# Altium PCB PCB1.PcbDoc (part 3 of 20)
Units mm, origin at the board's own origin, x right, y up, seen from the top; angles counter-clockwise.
Board outline 294.51 x 138.18 mm, 12 copper layers (Top Layer 1 _Signal, L2_GND, L3_Signals, L4_GND, L5_POWER, L6_Signals, L7_GND, L8_Signals, L9_GND, L10_POWER, L11_GND, Bottom Layer_Signals), stack 1.788 mm thick; 1254 components, 836 nets, 5699 pads, 2073 vias.
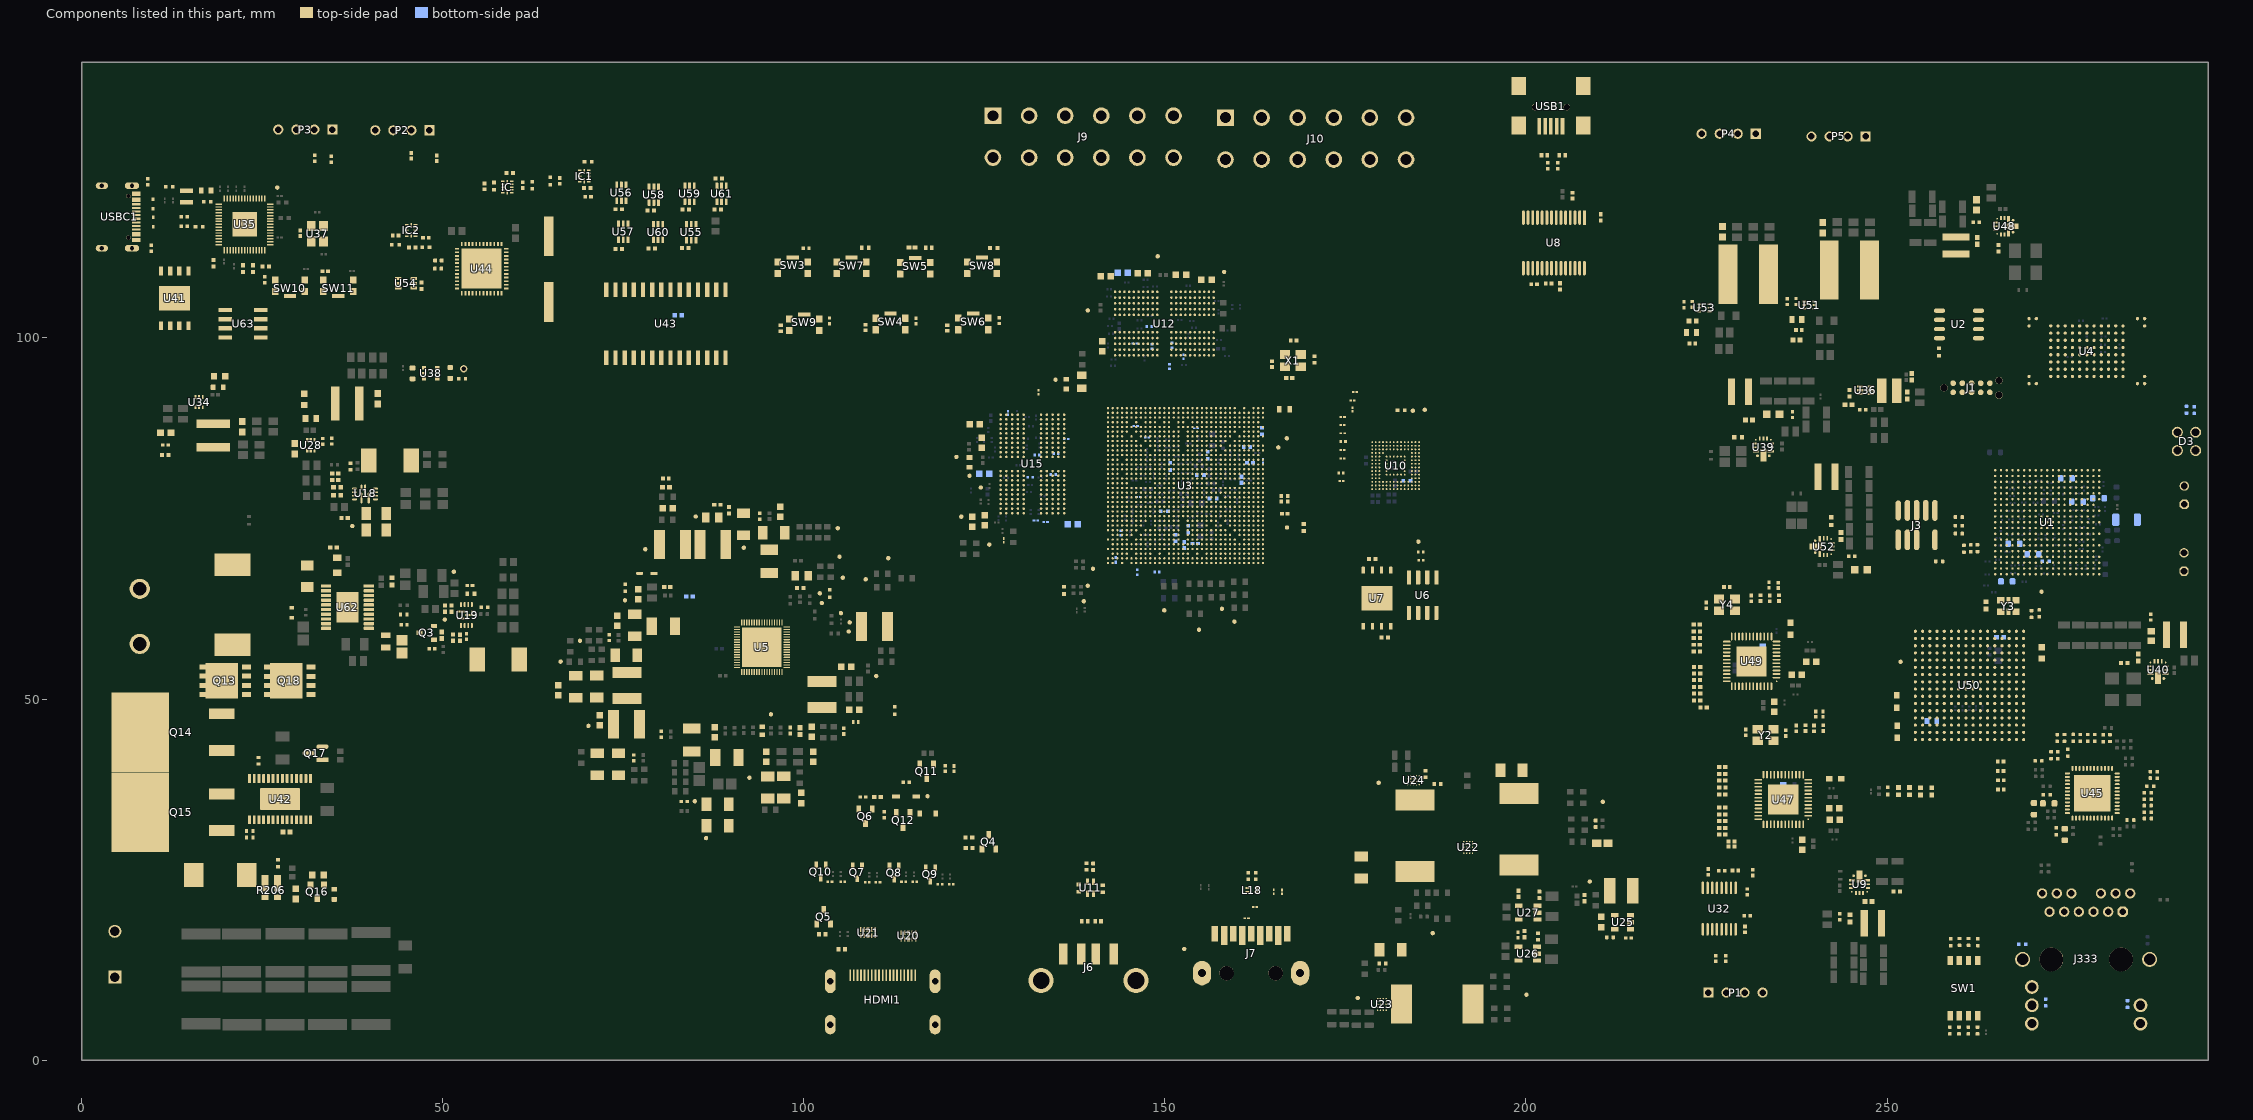
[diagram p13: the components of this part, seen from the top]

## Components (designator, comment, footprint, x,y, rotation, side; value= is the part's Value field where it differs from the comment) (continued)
C682 "GRM188R72A104KA35D" FP-GRM188-0_1-e0_2_0_5-IPC_B 227.217,114.688 r90 top
C683 "C0402C104M3PAC7867" FP-C0402-BB-MFG 47.673,113.869 r0 top value="0.10 μF"
C684 "C0402C104M3PAC7867" FP-C0402-BB-MFG 43.469,114.181 r180 top value="0.10 μF"
C685 "1uf 16V 0402" FP-CC0402-MFG 47.68,112.544 r0 top value="1 uF"
C686 "1uf 16V 0402" FP-CC0402-MFG 43.466,112.879 r180 top value="1 uF"
CN1 "DB910-7.62-2P-GN-S" CONN-TH_2P-P7.62_DB910-7.62-2P 7.239,61.742 r270 top value=30A
D1 "RF2945-000" FP-SESD0402-MFG 107.194,46.827 r0 top value=0.1pF
D2 "1N4148WS" FP-477AB-IPC_C 78.266,67.392 r180 top
D3 "LED_Dual_553-0123" DIO_LED_DUAL_553-0123 291.469,85.671 r270 top value="GREEN, YELLOW"
D4 "NSVR0320MW2T1G" ONSC-SOD-323-2-477-02_V 117.174,34.13 r180 top
D5 "LESD5D5.0CT1G" TVS_LESD5D5.0CT1G 9.875,118.545 r270 top
D6 "LESD5D5.0CT1G" TVS_LESD5D5.0CT1G 9.918,116.055 r270 top
D7 "B5819WS" FAIR-SOD-323_V 114.174,36.514 r180 top
D9 "BAS516,315" FP-SOD523-MFG 29.084,61.937 r90 top
D13 "5.0SMDJ60A" SMC_L6.9-W5.9-LS7.9-RD 19.187,25.64 r180 top
FB1 "Ferrite Bead" IND_C_0603 274.839,80.537 r0 bottom value=120R
FB2 "Ferrite Bead" IND_C_0603 279.288,77.807 r0 bottom value=33R
FB3 "Ferrite Bead" IND_C_0603 270.207,70.029 r180 bottom value=120R
FB4 "Ferrite Bead" IND_C_0603 276.364,77.334 r0 bottom value=120R
FB5 "Ferrite Bead" IND_C_0603 267.571,71.513 r180 bottom value=120R
FB6 "Ferrite Bead" IND_C_0603 266.581,66.293 r180 bottom value=120R
FB7 "Ferrite Bead" IND_C_1206 283.173,74.822 r180 bottom value=120R
FB9 "BLM18KG121TN1D" FP-BLM18-0_15-t0_6-d1_2-IPC_A 210.587,30.046 r180 top
FB24 "Ferrite Bead" IND_C_0603 272.379,35.539 r180 top value=120R
FB25 "Ferrite Bead" IND_C_0603 274.616,31.242 r90 top value=120R
FB26 "Ferrite Bead" IND_C_0603 270.349,34.789 r90 top value=120R
HDMI1 "" HDMI-SMD_HDMI-019S 110.926,6.417 r0 top
IC "NTS0104GU12,115" QFN40P170X200X50-12N 58.94,120.892 r0 top
IC1 "NTS0104GU12,115" QFN40P170X200X50-12N 69.602,122.418 r180 top
IC2 "NTS0104GU12,115" QFN40P170X200X50-12N 45.642,114.893 r180 top
J1 "CON-10P-TC2050-SMT-NO-LEGS" "CON_TAG TC2050 10P NO LEGS" 261.696,93.097 r0 top
J2 "Header 1x2" HDR_M_2.54_1x2 291.128,67.7 r90 top value="HDR-2.54 Male 1x2"
J3 "Header 2x5 POS 7 POLARIZED" HDR_M_1.27_2x5_SMD_V_SAM_FTSH-105-01-F-DV-007-K 254.091,74.08 r0 top value=FTSH-105-01-F-DV-007-K-P-TR
J5 "JUMPER" JUMPER 169.237,73.805 r180 top
J6 "62900416021" 62900416021 139.427,7.747 r0 top
J7 "692122030100" 692122030100 161.941,8.592 r0 top
J8 "1714955" PHOE-1714955_V 4.603,14.663 r90 top
J9 "B12P-XL(LF)(SN)" FP-B12P-XL_LF_SN-MFG 138.7,129.693 r180 top
J10 "B12P-XL(LF)(SN)" FP-B12P-XL_LF_SN-MFG 170.895,129.424 r180 top
J34 "Header 1x2" HDR_M_2.54_1x2 291.166,76.956 r90 top value="HDR-2.54 Male 1x2"
J333 "CON_RJ-45_L829-1J1T-43" CON_JACK_RJ45_L829-1J1T-43 270.056,7.59 r0 top value="MODULAR RJ45"
L1 "0.22uH/12A" FP-FDSD0415-MFG 89.342,41.892 r180 top
L2 "0.47uH/4A" FP-NRS5030-H_3_1-MFG 75.463,46.5 r180 top
L3 "0.47uH/4A" FP-NRS5030-H_3_1-MFG 81.831,71.37 r180 top
L4 "0.47uH/4A" FP-NRS5030-H_3_1-MFG 87.407,71.405 r180 top
L5 "0.22uH/12A" FP-FDSD0415-MFG 80.549,60.065 r180 top
L6 "XAL5030-222MEB" FP-XAL5030-222MEB-MFG 36.798,90.902 r0 top
L7 "0.47uH/4A" FP-NRS5030-H_3_1-MFG 102.538,50.641 r270 top
L8 "1uH 10A" WE-MAPI_4020 229.637,92.543 r0 top
L9 "1.5uH" WE-MAPI_3020 250.312,92.705 r0 top
L10 "0.47uH/4A" FP-NRS5030-H_3_1-MFG 109.772,60.058 r180 top
L11 "0.22uH/12A" FP-FDSD0415-MFG 84.503,44.343 r270 top
L12 "0.22uH/12A" FP-FDSD0415-MFG 95.231,69.067 r90 top
L13 "0.47uH/4A" FP-NRS5030-H_3_1-MFG 75.506,51.85 r90 top
L14 "2.2uH" FP-XAL5030-222MEB-MFG 18.227,86.488 r270 top
L15 "1uH 10A" WE-MAPI_4020 248.03,18.943 r180 top
L16 "1.5uH" IND-SMD_L7.1-W6.6 42.702,83.053 r0 top
L17 "1.5uH" IND-SMD_L7.1-W6.6 57.676,55.493 r0 top
L18 "MCZ1210AH900L2TA0G" FP-MCZ1210AH-MFG 162.054,23.542 r270 top
L19 "220nH" WE-HCC_1210 199.038,31.976 r90 top
L20 "220nH" WE-HCC_1210 187.688,7.77 r0 top
L21 "220nH" WE-HCC_1210 184.635,31.065 r270 top
L22 "2.2uH" IND-SMD_L4.0-W4.0 213.209,23.452 r180 top
L23 "1uH 10A" WE-MAPI_4020 289.859,58.913 r180 top
L24 "1uH 10A" WE-MAPI_4020 259.539,112.779 r90 top
L25 "3.3uH 800mA" FP-CB2016-MFG 14.491,119.587 r90 top
L26 "1uH 10A" WE-MAPI_4020 241.62,80.769 r0 top
L27 "SRN8040-2R2Y" BOUR-SRN8040_V 244.786,109.393 r0 top
L28 "SRN8040-2R2Y" BOUR-SRN8040_V 230.77,108.823 r0 top
L29 "SRP1265A-1R8M" FP-SRP1265A-MFG 20.896,63.05 r90 top value=1.8uH
P1 "S4B-XH-A(LF)(SN)" JST-S4B-XH-A(LF)(SN)_V 229.02,9.345 r0 top
P2 "S4B-XH-A(LF)(SN)" JST-S4B-XH-A(LF)(SN)_V 44.42,128.751 r180 top
P3 "S4B-XH-A(LF)(SN)" JST-S4B-XH-A(LF)(SN)_V 30.982,128.853 r180 top
P4 "S4B-XH-A(LF)(SN)" JST-S4B-XH-A(LF)(SN)_V 228.072,128.272 r180 top
P5 "S4B-XH-A(LF)(SN)" JST-S4B-XH-A(LF)(SN)_V 243.29,127.892 r180 top
Q3 "SS8050-G" FP-SS8050-G-MFG 47.782,59.157 r180 top
Q4 "2SK3018" SOT-23-3_L2.9-W1.3-P1.90-LS2.4-BR 547.187,460.843 r270 top
Q5 "2SK3018" SOT-23-3_L2.9-W1.3-P1.90-LS2.4-BR 524.315,450.472 r270 top
Q6 "2SK3018" SOT-23-3_L2.9-W1.3-P1.90-LS2.4-BR -313.018,-396.862 r90 top
Q7 "WNM6002-3/TR" SOT-323-3_L2.0-W1.3-P1.30-LS2.1-BR -235.455,-430.948 r90 top
Q8 "WNM6002-3/TR" SOT-323-3_L2.0-W1.3-P1.30-LS2.1-BR -230.348,-430.985 r90 top
Q9 "WNM6002-3/TR" SOT-323-3_L2.0-W1.3-P1.30-LS2.1-BR -225.329,-431.241 r90 top
Q10 "WNM6002-3/TR" SOT-323-3_L2.0-W1.3-P1.30-LS2.1-BR -240.485,-430.836 r90 top
Q11 "2SK3018" SOT-23-3_L2.9-W1.3-P1.90-LS2.4-BR -304.538,-390.614 r90 top
Q12 "2SK3018" SOT-23-3_L2.9-W1.3-P1.90-LS2.4-BR -307.813,-397.382 r90 top
Q13 "CSD18540Q5B" VSON-CLIP-8_L5.0-W6.0-P1.27-BL 19.88,52.514 r90 top
Q14 "PSMN4R8" TO-263-2_L10.2-W8.5-P2.54-LS15.2-TL 12.748,45.416 r180 top
Q15 "PSMN4R8" TO-263-2_L10.2-W8.5-P2.54-LS15.2-TL 12.748,34.317 r180 top
Q16 "2N7002-7-F" FP-SOT23-MFG 32.632,23.314 r270 top
Q17 "MMBT3904-7-F" FP-SOT23-IPC_A 32.377,42.495 r180 top
Q18 "CSD18540Q5B" VSON-CLIP-8_L5.0-W6.0-P1.27-BL 28.828,52.492 r90 top
R1 "Resistor" RES_C_0402 262.522,70.885 r90 top value=10k
R2 "10R 0402" FP-RT0402-MFG 257.201,98.051 r90 top value=10Ω
R3 "100K / 0402" FP-CRGP0402-IPC_C 161.806,82.693 r0 bottom value=100KΩ
R4 "Resistor" RES_C_0402 271.077,61.858 r90 top value=10k
R5 "Resistor" RES_C_0402 259.945,75.196 r180 top value=10k
R6 "Resistor" RES_C_0402 270.003,61.769 r90 top value=10k
R7 "Resistor" RES_C_0402 260.648,70.814 r90 top value=10k
R8 "Resistor" RES_C_0402 257.223,69.053 r0 top value=10k
R9 "0R/0201" FP-RMCF0201-IPC_C 163.589,82.97 r90 bottom
R10 "Resistor" RES_C_0402 262.524,4.097 r90 top value=1k
R11 "Resistor" RES_C_0402 259.945,74.011 r0 top value=0R
R12 "Resistor" RES_C_0402 261.254,4.097 r90 top value=1k
R13 "Resistor" RES_C_0402 259.971,4.097 r90 top value=1k
R14 "Resistor" RES_C_0402 259.945,72.911 r0 top value=0R
R15 "Resistor" RES_C_0402 258.701,4.097 r90 top value=1k
R16 "Resistor" RES_C_0402 262.573,16.336 r270 top value=10k
R17 "Resistor" RES_C_0402 261.29,16.359 r270 top value=10k
R18 "Resistor" RES_C_0402 260.043,16.359 r270 top value=10k
R19 "Resistor" RES_C_0402 258.82,16.324 r270 top value=10k
R20 "120K 5% 0402(1005)" RESC0402(1005)_M 94.228,45.592 r90 top value="120000.00 Ohm"
R21 "Resistor" RES_C_0402 292.547,90.016 r270 bottom value=1k
R22 "Resistor" RES_C_0402 291.467,90.063 r270 bottom value=1k
R23 "510k/0402" RESC1005X40X25NL05T10 167.219,94.436 r0 top
R24 "22R2J" RESC0402(1005)_L#1 163.437,87.128 r90 bottom value=22
R25 "22R2J" RESC0402(1005)_L#1 161.349,84.868 r180 bottom value=22
R26 "22R2J" RESC0402(1005)_L#1 170.71,97.029 r270 top value=22
R27 "49.9R 0201" FP-AF0201-MFG 134.547,81.112 r180 bottom
R28 "100R / 0402" FP-MCS0402-IPC_C 80.239,45.119 r270 top
R29 "100R / 0402" FP-MCS0402-IPC_C 76.471,41.854 r90 top
R30 "0R 0805" FP-AF0805-IPC_B 99.72,67.063 r180 top
R31 "0R 0805" FP-AF0805-IPC_B 87.311,75.116 r0 top
R32 "120k/0402/1%" RESC1005X40X25ML05T10 80.902,79.316 r180 top
R33 "100k / 0402" FP-CRGP0402-IPC_C 88.031,76.916 r0 top value=100KΩ
R34 "100R / 0402" FP-MCS0402-IPC_C 73.057,58.506 r270 top
R35 "20k/0402" RESC1005X40X25ML10T10 99.502,45.562 r270 top
R36 "100R / 0402" FP-MCS0402-IPC_C 83.446,35.814 r0 top
R37 "100k / 0402" FP-CRGP0402-IPC_C 98.108,45.637 r90 top value=100KΩ
R38 "100R / 0402" FP-MCS0402-IPC_C 93.921,75.299 r90 top
R39 "200K/0402" FP-AC0402-IPC_B 81.109,65.534 r180 top
R40 "200K/0402" FP-AC0402-IPC_B 84.184,64.197 r0 bottom
R41 "10K/0402" RESC1005X40X20NL05T10 99.507,65.402 r0 top
R42 "DNP" RES_C_0402 261.611,70.865 r270 top value=10k
R43 "1.82K" FP-CRCW0402-e3-IPC_A 244.856,19.632 r90 top
R44 "10K/0201" RESC0603X28X15LL05T05 145.858,99.212 r0 bottom
R45 "10K/0201" RESC0603X28X15LL05T05 152.588,97.414 r90 bottom
R46 "240R/0201" FP-RMCF0201-IPC_C 128.259,89.591 r90 bottom
R47 "240R/0201" FP-RMCF0201-IPC_C 132.509,92.481 r90 top
R48 "10K/0201" RESC0603X28X15LL05T05 127.687,71.951 r270 top
R49 "10K/0201" RESC0603X28X15LL05T05 136.359,85.993 r180 bottom
R50 "10KR 0402" RESC1005X40X25ML05T10 247.442,21.954 r0 top
R51 "240R/0201" FP-RMCF0201-IPC_C 133.497,74.534 r0 bottom
R52 "4.87K 0402" FP-CRCW0402-e3-IPC_C 243.456,19.856 r90 top
R53 "11.5K 0402" RESC1005X40X25NL05T05 251.33,23.356 r180 top
R54 "1.21K 0603" FP-RMCF0603-IPC_B 262.362,118.421 r270 top
R55 "100KR 0402" FP-CRCW0402-e3-IPC_C 34.635,85.707 r270 top
R56 "0R/0201" FP-RMCF0201-IPC_C 174.628,86.796 r180 top
R57 "0R/0201" FP-RMCF0201-IPC_C 174.622,89.049 r180 top
R58 "0R/0201" FP-RMCF0201-IPC_C 175.975,91.348 r180 top
R59 "0R/0201" FP-RMCF0201-IPC_C 174.597,83.315 r180 top
R60 "0R/0201" FP-RMCF0201-IPC_C 174.477,80.176 r180 top
R61 "0R/0201" FP-RMCF0201-IPC_C 175.985,90.087 r90 top
R62 "0R/0201" FP-RMCF0201-IPC_C 174.594,84.489 r180 top
R63 "0R/0201" FP-RMCF0201-IPC_C 174.616,87.923 r180 top
R64 "0R/0201" FP-RMCF0201-IPC_C 176.324,92.5 r180 top
R65 "RT0201BRE0710KL" FP-RT0201-MFG 174.689,85.639 r0 top value=10KΩ
R66 "10k 0402" FP-CRGCQ0402-IPC_C 166.599,75.652 r0 top value=10KΩ
R67 "RT0201BRE0710KL" FP-RT0201-MFG 174.389,81.322 r0 top value=10KΩ
R68 "22R2J" RESC0402(1005)_L#1 166.58,78.119 r180 top value=22
R69 "47D5KR2F" RESC0402(1005)_L#1 166.571,77.341 r0 top value=47.5k
R70 "0R/0201" FP-RMCF0201-IPC_C 146.329,77.949 r0 bottom
R71 "240R/0201" FP-RMCF0201-IPC_C 132.135,74.734 r0 bottom
R72 "10K/0402" RESC1005X40X20NL05T10 180.434,58.519 r0 top
R73 "10K/0402" RESC1005X40X20NL05T10 178.719,69.357 r180 top
R74 "0R 0402" FP-AF0402-MFG 138.098,23.812 r270 top
R75 "100k/0402" RESC1005X40X25NL05T10 36.413,75.068 r0 top
R76 "30k/0402/0.1%" RESC1005X35X20ML05T10 35.371,79.314 r180 top
R77 "232k 0402" RESC1005X40X25ML05T05 35.377,78.226 r0 top
R78 "3D3R2J" RESC0402(1005)_L#1 37.244,82.217 r90 top value=3.3
R79 "100k/0402" RESC1005X40X25NL05T10 35.13,80.322 r180 top
R80 "100k/0402" RESC1005X40X25NL05T10 35.125,81.242 r180 top
R81 "510k/0402" RESC1005X40X25NL05T10 51.208,62.519 r270 top
R82 "3D3R2J" RESC0402(1005)_L#1 55.787,62.708 r0 top value=3.3R
R83 "100k/0402" RESC1005X40X25NL05T10 51.435,58.501 r90 top
R84 "43k/0402" FP-AC0402-MFG 53.898,64.597 r0 top
R85 "100k/0402" RESC1005X40X25NL05T10 52.39,58.492 r90 top
R86 "100k/0402" RESC1005X40X25NL05T10 50.29,62.528 r90 top
R87 "10K/0402" RESC1005X40X25LL05T10 53.314,58.636 r90 top
R88 "7.5k/0402" RESC1005X40X25LL05T10 53.758,65.728 r180 top
R89 "10K/0402" RESC1005X40X25LL05T10 48.525,56.972 r180 top
R90 "Resistor 51k +/-5% 0402 63 mW" RESC1005X40X25ML05T10 49.887,58.829 r270 top value=51k
R91 "200R/0201" FP-RT0201-MFG 148.92,67.58 r0 bottom value=200Ω
R92 "0R/0201" FP-RMCF0201-IPC_C 161.325,19.636 r0 top
R93 "2R2/0402" RESC0402(1005)_L#1 161.547,25.516 r270 top
R94 "2R2/0402" RESC0402(1005)_L#1 162.586,25.511 r270 top
R95 "0R/0201" FP-RMCF0201-IPC_C 162.483,21.225 r180 top
R96 "0R/0201" FP-RMCF0201-IPC_C 166.233,23.302 r270 top
R97 "0R/0201" FP-RMCF0201-IPC_C 165.076,23.31 r270 top
R98 "8.2K/0201" RESC0603X26X15ML03T05 154.22,71.545 r180 bottom
R99 "8.2K/0201" RESC0603X28X15NL05T05 143.229,69.273 r90 bottom
R100 "47K/0402" FP-CRCW0402-e3-IPC_B 122.871,30.84 r180 top
R101 "Resistor" RES_C_0402 271.996,69.096 r0 bottom value=10R
R102 "47K/0402" FP-CRCW0402-e3-IPC_B 122.887,29.383 r180 top
R103 "1.2k/0402" FP-RN73R1E-IPC_B 105.258,15.343 r0 top
R104 "200R/0201" FP-RT0201-MFG 143.951,72.998 r270 bottom value=200Ω
R105 "47K/0402" FP-CRCW0402-e3-IPC_B 102.547,17.418 r180 top
R106 "1.8k 0402" FP-RN73R1E-IPC_C 111.121,33.965 r90 top
R107 "10K/0402" RESC1005X40X25LL05T10 108.189,36.447 r180 top
R108 "1.8k 0402" FP-RN73R1E-IPC_C 114.193,38.486 r180 top
R109 "590R 1% 0201(0603)" RESC0201(0603)_L 108.792,24.641 r0 top value="590.00 Ohm"
R110 "590R 1% 0201(0603)" RESC0201(0603)_L 110.254,24.655 r180 top value="590.00 Ohm"
R111 "590R 1% 0201(0603)" RESC0201(0603)_L 113.832,24.72 r0 top value="590.00 Ohm"
R112 "590R 1% 0201(0603)" RESC0201(0603)_L 115.363,24.689 r180 top value="590.00 Ohm"
R113 "1K/0402" FP-AC0402-IPC_C 119.593,40.374 r90 top
R114 "10K/0402" RESC1005X40X25LL05T10 120.813,40.356 r90 top
R115 "590R 1% 0201(0603)" RESC0201(0603)_L 118.863,24.38 r0 top value="590.00 Ohm"
R116 "590R 1% 0201(0603)" RESC0201(0603)_L 120.413,24.354 r180 top value="590.00 Ohm"
R117 "590R 1% 0201(0603)" RESC0201(0603)_L 103.608,24.692 r0 top value="590.00 Ohm"
R118 "590R 1% 0201(0603)" RESC0201(0603)_L 105.394,24.708 r180 top value="590.00 Ohm"
R119 "AC0402FR-7W27KL" FP-AC0402-IPC_B 110.213,36.42 r180 top
R120 "100R / 0402" RESC0402(1005)_L#1 209.651,32.724 r90 top value=100
R121 "100R / 0402" RESC0402(1005)_L#1 180.156,13.384 r0 top value=100
R122 "100k/0402" RESC1005X40X25NL05T10 160.596,80.363 r90 bottom
R123 "120k/0402" RESC0402(1005)_L#1 186.081,39.63 r270 top value=120k
R124 "100R / 0402" RESC0402(1005)_L#1 187.747,38.229 r0 top value=100
R125 "100k/0402" RESC1005X40X25NL05T10 208.107,22.427 r270 top
R126 "10uf/0603" FP-CC0603-DC-MFG 210.42,19.126 r270 top
R127 "10K/0402" RESC1005X40X25LL05T10 214.194,16.917 r180 top
R128 "10K/0402" RESC1005X40X20NL05T10 151.489,72.297 r90 bottom
R129 "120k/0402" RESC0402(1005)_L#1 211.64,17.009 r0 top value=120k
R130 "100K / 0402" FP-CRGP0402-IPC_C 152.673,71.321 r270 bottom value=100KΩ
R131 "4.7k 0402" RESC0402(1005)_L#1 201.671,17.124 r270 top value=4.7k
R132 "4.7k 0402" RESC0402(1005)_L#1 201.875,22.893 r270 top value=4.7k
R133 "10K/0402" RESC1005X40X25LL05T10 198.883,17.318 r90 top
R134 "100k/0402" RESC1005X40X25NL05T10 199.794,17.451 r90 top
R135 "100k/0402" RESC1005X40X25NL05T10 198.999,23.04 r90 top
R136 "220K 0603" RESC1608X55X25ML10T15 31.738,88.845 r0 top
R137 "17.4K" RESC1005X40X25LL05T05 33.409,85.663 r90 top
R138 "30K" FP-AT0603-IPC_B 30.817,91.496 r270 top
R139 "10KR 0402" RESC1005X40X25ML05T10 253.43,94.621 r90 top
R140 "100KR 0402" FP-CRCW0402-e3-IPC_C 246.632,90.062 r0 top
R141 "10KR 0402" RESC1005X40X25ML05T10 252.788,92.035 r90 top
R142 "68.1K 0402" FP-CRCW0402-e3-IPC_B 244.824,92.354 r90 top
R143 "10KR 0402" RESC1005X40X25ML05T10 244.675,90.739 r0 top
R144 "30K" FP-AT0603-IPC_B 19.103,94.7 r0 top
R145 "RT0603BRD07135KL" RESC0603(1608)_L 18.907,93.161 r0 top value=135kΩ
R146 "100KR 0402" FP-CRCW0402-e3-IPC_C 11.62,85.17 r180 top
R147 "CRCW040220K0FKED" FP-CRCW0402-e3-IPC_B 11.575,83.798 r0 top
R148 "Resistor 0R +/- 5% 1206 250 mW" RESC3216X60X45ML15T20 71.419,40.977 r90 top value=0
R149 "HoYH1206-1W-10mR-1%" RESC3216X60X45ML15T20 74.339,40.977 r90 top value=1W
R150 "49.9R 0201" FP-AF0201-MFG 131.361,80.709 r0 bottom
R151 "49.9R 0201" FP-AF0201-MFG 134.917,83.991 r180 bottom
R152 "49.9R 0201" FP-AF0201-MFG 132.283,83.806 r180 bottom
R153 "49.9R 0201" FP-AF0201-MFG 148.217,98.83 r90 bottom
R154 "49.9R 0201" FP-AF0201-MFG 147.848,101.571 r0 bottom
R155 "49.9R 0201" FP-AF0201-MFG 151.015,98.978 r90 bottom
R156 "49.9R 0201" FP-AF0201-MFG 150.661,96.044 r90 bottom
R157 "4.87K 0402" FP-CRCW0402-e3-IPC_C 286.489,61.348 r270 top
R158 "604R 0603" RESC1609X50X30ML10T20 286.586,58.716 r270 top
R159 "11.5K 0402" RESC1005X40X25NL05T05 282.873,54.955 r0 top
R160 "10KR 0402" RESC1005X40X25ML05T10 284.775,55.732 r270 top
R161 "10KR 0402" RESC1005X40X25ML05T10 262.505,113.451 r270 top
R162 "4.87K 0402" FP-CRCW0402-e3-IPC_C 262.362,116.034 r0 top
R163 "11.5K 0402" RESC1005X40X25NL05T05 265.444,112.418 r90 top
R164 "0R/0402" RESC1005X40X25NL05T10 210.356,116.683 r90 top
R165 "0R/0402" RESC1005X40X25NL05T10 204.745,107.141 r90 top
R166 "22R/0402" FP-CRCW0402-e3-IPC_C 204.376,123.832 r90 top
R167 "22R/0402" FP-CRCW0402-e3-IPC_C 203.02,123.853 r90 top
R168 "22R/0402" FP-CRCW0402-e3-IPC_C 227.666,14.073 r270 top
R169 "22R/0402" FP-CRCW0402-e3-IPC_C 226.302,14.073 r270 top
R170 "22R/0402" FP-CRCW0402-e3-IPC_C 230.641,19.986 r0 top
R171 "22R/0402" FP-CRCW0402-e3-IPC_C 230.65,23.287 r90 top
R172 "10K/0402" RESC1005X40X20NL05T10 89.648,76.152 r270 top
R173 "2R2/0402" RESC0402(1005)_L#1 139.133,26.792 r270 top
R174 "2R2/0402" RESC0402(1005)_L#1 140.079,26.775 r270 top
R175 "0R 0402" FP-AF0402-MFG 141.418,23.721 r270 top
R176 "200R/0201" FP-RT0201-MFG 146.177,67.561 r270 bottom value=200Ω
R177 "100R / 0402" FP-MCS0402-IPC_C 100.316,112.425 r180 top
R178 "3K 0402" FP-AT0402-IPC_B 114.984,112.503 r0 top
R179 "100R / 0402" FP-MCS0402-IPC_C 115.538,102.346 r90 top
R180 "6.8K 0402" FP-AC0402-MFG 108.517,112.497 r0 top
R181 "100R / 0402" FP-MCS0402-IPC_C 127.043,102.392 r90 top
R182 "12k 0402" FP-CRCW0402-e3-MFG 126.31,112.457 r180 top
R183 "100R / 0402" FP-MCS0402-IPC_C 103.568,102.363 r90 top
R184 "6.04K  0603" FP-RC0603-0_55-IPC_A 234.229,89.423 r0 top
R185 "10KR 0402" RESC1005X40X25ML05T10 230.889,88.643 r180 top
R186 "4.87K 0402" FP-CRCW0402-e3-IPC_C 236.914,89.383 r270 top
R187 "R220" RESC1005X40X25NL05T10 227.194,39.622 r0 top
R188 "33R 0603" FP-AF0603-IPC_C 17.241,120.431 r180 top
R189 "RC0402JR-100RL" RESC1005X40X25NL05T10 223.671,56.596 r0 top
R190 "5.1K 0402" FP-RN73R1E-IPC_C 9.65,112.393 r270 top value=5.1K
R191 "51R 0402" FP-AF0402-IPC_C 49.205,124.883 r90 top
R192 "5.1K 0402" FP-RN73R1E-IPC_C 9.14,121.649 r270 top value=5.1K
R193 "51R 0402" FP-AF0402-IPC_C 45.634,125.229 r90 top
R194 "3.3K 0402" FP-RN73R1E-IPC_B 23.745,109.611 r270 top
R195 "3.3K 0402" FP-RN73R1E-IPC_B 22.373,109.609 r270 top
R196 "10K/0402" RESC1005X40X20NL05T10 25.509,109.873 r180 top
R197 "1k 0402" FP-MCS0402-IPC_C 25.356,108.062 r90 top
R198 "22R/0402" FP-CRCW0402-e3-IPC_C 14.209,116.782 r0 top
R199 "22R/0402" FP-CRCW0402-e3-IPC_C 14.219,115.455 r0 top
R200 "1k" FP-CRGCQ0402-IPC_C 30.27,114.498 r270 top value=1KΩ
R201 "22R/0402" FP-CRCW0402-e3-IPC_C 34.543,124.751 r90 top
R202 "22R/0402" FP-CRCW0402-e3-IPC_C 32.282,124.881 r90 top
R203 "10K/0402" RESC1005X40X20NL05T10 18.257,110.368 r270 top
R204 "1k" FP-CRGCQ0402-IPC_C 33.765,109.251 r0 top value=1KΩ
R205 "4R99 1% 0402(1005)" RESC0402(1005)_L#2 23.276,30.805 r0 top value="4.99 Ohm"
R206 "0.001R 1206" FP-PS0612-MFG 26.259,23.907 r180 top value=1mΩ
R207 "4R99 1% 0402(1005)" RESC0402(1005)_L#2 23.293,31.72 r0 top value="4.99 Ohm"
R208 "100K 0603" FP-TFCR0603-IPC_B 29.659,23.031 r90 top
R209 "95.3K 0402" FP-RP73P-1E-MFG 27.192,27.268 r270 top value=95.3KΩ
R210 "14.3K 0603" RESC0603(1608)_L 34.974,22.95 r270 top value=14.3K
R211 "8.87K 0402" FP-RC1005-IPC_A 28.382,31.601 r180 top
R212 "28K 1% 0402(1005)" RESC0402(1005)_L#2 24.499,41.437 r90 top value="28000.00 Ohm"
R213 "100K 1% 0603(1608)" RESC0603(1608)_N 32.745,25.635 r0 top value="100000.00 Ohm"
R214 "20K 0402" RESC1005X35X20ML05T10 82.617,103.123 r180 bottom
R215 "11K 0603" FP-RT0603-MFG 242.822,38.969 r0 top value=11KΩ
R216 "RC0402JR-100RL" RESC1005X40X25NL05T10 227.191,36.767 r0 top
R217 "RC0402JR-100RL" RESC1005X40X25NL05T10 228.464,30.245 r0 top
R218 "RC0402JR-100RL" RESC1005X40X25NL05T10 227.198,37.732 r0 top
R219 "RC0402JR-100RL" RESC1005X40X25NL05T10 227.195,38.692 r0 top
R220 "RC0402JR-100RL" RESC1005X40X25NL05T10 223.699,49.789 r0 top
R221 "RC0402JR-100RL" RESC1005X40X25NL05T10 227.193,40.57 r0 top
R222 "RC0402JR-100RL" RESC1005X40X25NL05T10 227.181,34.985 r0 top
R223 "RC0402JR-100RL" RESC1005X40X25NL05T10 228.463,29.561 r0 top
R224 "RC0402JR-100RL" RESC1005X40X25NL05T10 227.177,34.035 r0 top
R225 "RC0402JR-100RL" RESC1005X40X25NL05T10 227.18,33.097 r0 top
R226 "RC0402JR-100RL" RESC1005X40X25NL05T10 227.176,32.157 r0 top
R227 "RC0402JR-100RL" RESC1005X40X25NL05T10 227.176,31.238 r0 top
R228 "12.1R 0402" RESC1005X40X25LL05T10 241.136,47.9 r270 top
R229 "12.1R 0402" RESC1005X40X25LL05T10 240.138,47.9 r270 top
R230 "14.3K 0402" FP-CRCW0402-e3-MFG 229.381,86.236 r0 top
R231 "6.04K  0603" FP-RC0603-0_55-IPC_A 246.4,67.921 r180 top
R232 "10KR 0402" RESC1005X40X25ML05T10 243.626,72.562 r90 top
R233 "4.87K 0402" FP-CRCW0402-e3-IPC_C 245.107,69.749 r180 top
R234 "14.3K 0402" FP-CRCW0402-e3-MFG 242.273,74.632 r270 top
R235 "11K 0603" FP-RT0603-MFG 236.626,59.717 r90 top value=11KΩ
R236 "RC0402JR-100RL" RESC1005X40X25NL05T10 223.663,57.514 r0 top
R237 "RC0402JR-100RL" RESC1005X40X25NL05T10 223.667,58.443 r0 top
R238 "RC0402JR-100RL" RESC1005X40X25NL05T10 223.666,59.369 r0 top
R239 "RC0402JR-100RL" RESC1005X40X25NL05T10 223.658,60.307 r0 top
R240 "RC0402JR-100RL" RESC1005X40X25NL05T10 223.696,54.46 r0 top
R241 "RC0402JR-100RL" RESC1005X40X25NL05T10 224.605,48.819 r0 top
R242 "620R 0603" FP-AC0603-IPC_C 256.217,46.943 r180 bottom
R243 "RC0402JR-100RL" RESC1005X40X25NL05T10 223.695,53.558 r0 top
R244 "RC0402JR-100RL" RESC1005X40X25NL05T10 223.686,52.616 r0 top
R245 "RC0402JR-100RL" RESC1005X40X25NL05T10 223.689,51.676 r0 top
R246 "RC0402JR-100RL" RESC1005X40X25NL05T10 223.689,50.737 r0 top
R247 "Resistor 0R +/- 5% 1206 250 mW" RESC3216X60X45ML15T20 95.01,37.744 r270 top value=0
R248 "HoYH1206-1W-10mR-1%" RESC3216X60X45ML15T20 97.246,37.765 r270 top value=1W
R249 "12.1R 0402" RESC1005X40X25LL05T10 234.952,65.748 r270 top
R250 "4.7k/0402" FP-MCS0402-IPC_A 263.715,62.975 r90 top
R251 "12.1R 0402" RESC1005X40X25LL05T10 233.653,65.774 r270 top
R252 "4.7k/0402" FP-MCS0402-IPC_A 265.659,58.554 r0 bottom
R253 "RMCF0603ZT0R00 0R/0603" FP-RMCF0603-MFG 166.56,90.097 r180 top value=0mΩ
R254 "95.3kΩ 0402" FP-CRCW0402-e3-IPC_A 237.46,99.717 r180 top
R255 "100kΩ, 0402" FP-CRCW0402-e3-IPC_C 236.185,105.031 r90 top
R256 "2K 0603" FP-AC0603-IPC_B 271.409,56.394 r90 top
R257 "4.7k/0402" FP-MCS0402-IPC_A 251.603,37.237 r270 top
R258 "332R 0603" FP-RT0603-MFG 251.344,49.64 r90 top value=332Ω
R259 "4.7k/0402" FP-MCS0402-IPC_A 256.19,37.212 r270 top
R260 "332R 0603" FP-RT0603-MFG 251.412,45.463 r90 top value=332Ω
R261 "4.7k/0402" FP-MCS0402-IPC_A 254.632,37.218 r270 top
R262 "4.7k/0402" FP-MCS0402-IPC_A 253.128,37.246 r270 top
R263 "0R 0805" FP-AF0805-IPC_B 138.491,93.918 r270 top
R264 "0R 0603" FP-AC0603-IPC_C 122.927,82.762 r90 top
R265 "0R 0603" FP-AC0603-IPC_C 136.337,93.613 r270 top
R266 "" FP-MCT0603-MFG 237.515,102.566 r0 top value=30K
R267 "59K 0402" RESC1005X40X25LL05T05 237.411,105.046 r270 top
R268 "95.3kΩ 0402" FP-CRCW0402-e3-IPC_A 223.068,102.324 r180 top
R269 "100kΩ, 0402" FP-CRCW0402-e3-IPC_C 221.885,104.601 r90 top
R270 "" FP-MCT0603-MFG 222.919,100.734 r0 top value=30K
R271 "59K 0402" RESC1005X40X25LL05T05 223.035,104.653 r270 top
R272 "10K/0402" RESC1005X40X20NL05T10 47.089,107.218 r270 top
R273 "10k 0402" RESC1005X40X20NL05T10 45.753,112.527 r180 top
R274 "240R/0201" FP-RMCF0201-IPC_C 147.523,86.186 r180 bottom
R275 "240R/0201" FP-RMCF0201-IPC_C 154.294,87.49 r0 bottom
R276 "10K/0402" RESC1005X40X20NL05T10 83.582,112.43 r180 top
R277 "10k 0402" RESC1005X40X20NL05T10 59.318,122.854 r180 top
R278 "10K/0402" RESC1005X40X20NL05T10 74.407,117.818 r180 top
R279 "10K/0402" RESC1005X40X20NL05T10 74.398,112.33 r180 top
R280 "10K/0402" RESC1005X40X20NL05T10 78.805,117.657 r180 top
R281 "10K/0402" RESC1005X40X20NL05T10 83.681,117.812 r180 top
R282 "10K/0402" RESC1005X40X20NL05T10 78.961,112.389 r180 top
R283 "10k 0402" RESC1005X40X20NL05T10 70.017,120.771 r180 top
R284 "10K/0402" RESC1005X40X20NL05T10 88.106,117.759 r180 top
R285 "10K/0402" RESC1005X40X20NL05T10 88.21,122.077 r0 top
R286 "Resistor 0R +/- 5% 1206 250 mW" RESC3216X60X45ML15T20 75.422,56.079 r0 top value=0
R287 "HoYH1206-1W-10mR-1%" RESC3216X60X45ML15T20 76.598,60.21 r270 top value=1W
R288 "Resistor 0R +/- 5% 1206 250 mW" RESC3216X60X45ML15T20 88.07,35.428 r0 top value=0
R289 "HoYH1206-1W-10mR-1%" RESC3216X60X45ML15T20 88.07,32.474 r0 top value=1W
R290 "Resistor 0R +/- 5% 1206 250 mW" RESC3216X60X45ML15T20 91.647,74.188 r270 top value=0
R291 "HoYH1206-1W-10mR-1%" RESC3216X60X45ML15T20 95.857,73.004 r180 top value=1W
R292 "Resistor 0R +/- 5% 1206 250 mW" RESC3216X60X45ML15T20 71.328,51.721 r270 top value=0
R293 "HoYH1206-1W-10mR-1%" RESC3216X60X45ML15T20 68.423,51.707 r270 top value=1W
R294 "CRCW080539K2FKEA" FP-CRCW0805-e3-IPC_C 42.127,57.984 r270 top
R295 "CRCW04021M00FKED" CRCW0402-e3_MFG 44.603,61.694 r0 top
R296 "AC0402FR-0786K6L" FP-AC0402-IPC_B 34.872,70.966 r180 top
R297 "RNCP0805FTD4K75" FP-RNCP0805-IPC_A 44.343,57.266 r90 top
R298 "CRCW04025K23FKED" FP-CRCW0402-e3-IPC_C 44.663,60.277 r180 top
R299 "CSNL1206FT2L00" RESC3116X70X50ML13T20 31.224,67.014 r270 top value=2mΩ
R300 "CRCW0402147KFKED" FP-CRCW0402-e3-IPC_A 42.987,66.293 r270 top
R301 "RT0201FRE072K2L" FP-RT0201-MFG 185.482,69.214 r180 top value=2.2KΩ
R302 "RT0805FRE079K76L" FP-RT0805-MFG 35.411,68.537 r90 top value=9.76KΩ
R303 "240R/0201" FP-RMCF0201-IPC_C 145.96,87.82 r0 bottom
R304 "RT0201FRE072K2L" FP-RT0201-MFG 185.444,70.336 r180 top value=2.2KΩ
R305 "22R2J" RESC0402(1005)_L#1 49.39,110.717 r0 top value=22
R306 "22R2J" RESC0402(1005)_L#1 49.373,109.582 r0 top value=22
R307 "HoYH1206-1W-10mR-1%" RESC3216X60X45ML15T20 198,40.145 r180 top value=1W
R308 "HoYH1206-1W-10mR-1%" RESC3216X60X45ML15T20 181.263,15.281 r180 top value=1W
R309 "HoYH1206-1W-10mR-1%" RESC3216X60X45ML15T20 177.201,26.658 r270 top value=1W
R334 "Resistor" RES_C_0603 45.827,95.088 r270 top value=100k
R335 "Resistor" RES_C_0603 51.046,95.159 r90 top value=15k
R339 "Resistor" RES_C_0402 52.689,94.359 r0 top value=10k
R374 "Resistor" RES_C_0402 272.712,42.216 r90 top value=10k
R375 "Resistor" RES_C_0402 273.652,42.222 r270 top value=1k
R376 "Resistor" RES_C_0402 279.942,44.569 r90 top value=10k
R377 "Resistor" RES_C_0402 280.867,44.592 r270 top value=1k
R381 "Resistor" RES_C_0402 277.799,44.614 r90 top value=10k
R382 "Resistor" RES_C_0402 278.754,44.614 r270 top value=1k
R383 "Resistor" RES_C_0402 276.769,44.614 r90 top value=10k
R384 "Resistor" RES_C_0402 275.783,44.622 r270 top value=1k
R385 "Resistor" RES_C_0402 274.565,44.614 r90 top value=10k
R386 "Resistor" RES_C_0402 273.558,44.607 r270 top value=1k
R387 "Resistor" RES_C_0402 286.098,35.246 r0 top value=10k
R388 "Resistor" RES_C_0402 286.098,36.136 r180 top value=1k
R389 "Resistor" RES_C_0402 286.1,37.015 r0 top value=10k
R390 "Resistor" RES_C_0402 286.462,37.94 r180 top value=1k
R391 "Resistor" RES_C_0402 286.947,39.95 r0 top value=10k
R392 "Resistor" RES_C_0402 286.947,39.05 r180 top value=1k
R393 "Resistor" RES_C_0402 283.7,33.239 r0 top value=1k
R394 "Resistor" RES_C_0402 286.116,33.457 r180 top value=1k
R395 "Resistor" RES_C_0402 272.106,36.734 r180 top value=10k
R396 "Resistor" RES_C_0402 275.043,42.576 r270 top value=1k
R397 "Resistor" RES_C_0402 286.087,34.323 r180 top value=1k
R398 "Resistor" RES_C_0402 283.303,7.771 r90 bottom value=330R
R399 "Resistor" RES_C_0402 268.715,16.03 r180 bottom value=330R
R400 "Resistor" RES_C_0402 270.972,41.434 r180 top value=0R
R401 "Resistor" RES_C_0402 271.962,7.974 r90 bottom value=330R
R402 "Resistor" RES_C_0402 273.427,31.686 r90 top value=6.04k
SW1 "Switch DIP 4 Pos" "SW_SMD_1.27MM X 4 copal" 260.646,9.963 r180 top value="DIP 4 SPST"
SW3 "KMR442G ULC LFS" FP-KMR442G_ULC_LFS-MFG 98.477,109.719 r0 top
SW4 "KMR442G ULC LFS" FP-KMR442G_ULC_LFS-MFG 112.016,101.937 r0 top
SW5 "KMR442G ULC LFS" FP-KMR442G_ULC_LFS-MFG 115.431,109.647 r0 top
SW6 "KMR442G ULC LFS" FP-KMR442G_ULC_LFS-MFG 123.469,101.945 r0 top
SW7 "KMR442G ULC LFS" FP-KMR442G_ULC_LFS-MFG 106.621,109.714 r0 top
SW8 "KMR442G ULC LFS" FP-KMR442G_ULC_LFS-MFG 124.693,109.716 r0 top
SW9 "KMR442G ULC LFS" FP-KMR442G_ULC_LFS-MFG 100.068,101.829 r0 top
SW10 "KMR442G ULC LFS" FP-KMR442G_ULC_LFS-MFG 28.857,107.214 r180 top
SW11 "KMR442G ULC LFS" FP-KMR442G_ULC_LFS-MFG 35.543,107.219 r180 top
TP2 "TPAD6R" TP06R#1 104.949,69.703 r90 top
TP6 "TPAD6R" TP06R#1 165.707,84.845 r90 top
TP7 "TPAD6R" TP06R#1 166.89,86.097 r90 top
TP8 "TPAD6R" TP06R#1 251.884,55.156 r0 top
TP9 "TPAD6R" TP06R#1 27.093,120.813 r90 top
TP10 "TPAD6R" TP06R#1 92.468,39.103 r270 top
TP13 "TPAD6R" TP06R#1 70.184,46.284 r180 top
TP14 "TPAD6R" TP06R#1 78.061,70.738 r90 top
TP15 "TPAD6R" TP06R#1 110.027,53.175 r90 top
TP16 "TPAD6R" TP06R#1 51.546,67.634 r90 top
TP17 "TPAD6R" TP06R#1 69.012,58.064 r90 top
TP18 "TPAD6R" TP06R#1 85.031,75.262 r90 top
TP20 "TPAD6R" TP06R#1 117.143,36.546 r90 top
TP21 "Test Point No BOM" TP_1x0.6 52.909,95.731 r0 top value="TP TH D1H0.6"
TP22 "TPAD6R" TP06R#1 185.111,71.79 r270 top
TP23 "TPAD6R" TP06R#1 179.604,38.396 r180 top
TP25 "TPAD6R" TP06R#1 84.912,35.843 r0 top
TP27 "TPAD6R" TP06R#1 105.147,61.894 r90 top
TP28 "TPAD6R" TP06R#1 102.217,64.637 r270 top
TP29 "TPAD6R" TP06R#1 102.503,63.292 r90 top
TP31 "TPAD6R" TP06R#1 104.705,73.653 r270 top
TP35 "TPAD6R" TP06R#1 95.454,47.878 r90 top
TP36 "TPAD6R" TP06R#1 66.33,55.179 r270 top
TP37 "TPAD6R" TP06R#1 75.237,63.671 r270 top
TP38 "TPAD6R" TP06R#1 106.354,60.61 r90 top
TP39 "TPAD6R" TP06R#1 105.403,66.802 r270 top
TP41 "TPAD6R" TP06R#1 271.399,64.862 r270 top
TP42 "TPAD6R" TP06R#1 185.985,90.045 r90 top
TP43 "TPAD6R" TP06R#1 184.338,89.921 r90 top
TP45 "TPAD6R" TP06R#1 166.915,73.749 r180 top
TP46 "TPAD6R" TP06R#1 108.577,66.581 r90 top
TP48 "TPAD6R" TP06R#1 149.918,62.281 r270 top
TP49 "TPAD6R" TP06R#1 125.688,71.377 r90 top
TP50 "TPAD6R" TP06R#1 91.695,70.954 r180 top
TP51 "TPAD6R" TP06R#1 157.903,62.488 r90 top
TP52 "TPAD6R" TP06R#1 159.631,60.717 r90 top
TP53 "TPAD6R" TP06R#1 86.472,30.741 r90 top
TP54 "TPAD6R" TP06R#2 154.732,59.591 r90 bottom
TP55 "TPAD6R" TP06R#1 140.039,68.027 r270 top
TP56 "TPAD6R" TP06R#1 122.957,80.905 r270 top
TP57 "TPAD6R" TP06R#1 134.858,94.212 r180 top
TP59 "TPAD6R" TP06R#1 139.321,65.685 r180 top
TP60 "TPAD6R" TP06R#1 111.706,69.505 r270 top
TP61 "TPAD6R" TP06R#1 138.778,63.54 r180 top
TP62 "TPAD6R" TP06R#1 124.514,79.282 r90 top
TP63 "TPAD6R" TP06R#1 121.136,83.522 r90 top
TP64 "TPAD6R" TP06R#1 121.816,75.252 r90 top
TP65 "TPAD6R" TP06R#1 37.49,73.952 r270 top
TP66 "TPAD6R" TP06R#1 50.294,60.993 r90 top
TP67 "TPAD6R" TP06R#1 106.217,59.347 r90 top
TP68 "TPAD6R" TP06R#1 152.676,15.388 r270 top
TP71 "TPAD6R" TP06R#1 176.712,8.592 r0 top
TP72 "TPAD6R" TP06R#1 210.646,35.771 r270 top
TP74 "TPAD6R" TP06R#1 200.064,9.055 r90 top
TP75 "TPAD6R" TP06R#1 187.09,17.58 r0 top
TP76 "TPAD6R" TP06R#1 208.844,24.718 r90 top
TP81 "TPAD6R" TP06R#1 158.201,109.134 r0 top
TP82 "TPAD6R" TP06R#1 139.333,103.814 r0 top
TP83 "TPAD6R" TP06R#1 149.005,111.306 r0 top
U1 "LAN9696RED-V/3KW" BGA-356_P0.8_17x17x1.68 272.181,74.48 r270 top locked
U2 "SST26WFXXX SOIC-8" SOIC-8 259.962,101.867 r180 top value=SST26WF016
U3 "RK3588" BGA1088C65P34X34_2300X2300X204N 152.854,79.553 r0 top locked
U4 "eMMC MLC NAND flash 200MHz" FBGA-100_14x18 277.672,98.169 r270 top value=IS21ES04G-JQLI
U5 "RK806-1" QFN35P700X700X90-69N 94.199,57.17 r180 top
U6 "ATECC608B-SSHDA-T" SOIC127P600X175-8N 185.7,64.377 r90 top
U7 "W25Q512JVEIQ" SON127P600X800X80-9N 179.375,63.962 r90 top
U8 "FT232RL-REEL" FP-SSOP-28-MFG 203.866,113.164 r270 top
U9 "PTPS62918RPYR" RPY0014A-MFG 246.188,24.538 r90 top
U10 "SDINBDA4-64G" FBGA-153_L13.0-W11.5-P0.50_KLMAG1JETD-B041 181.764,82.446 r0 top locked
U11 "" FILTER-SMD_4P-L2.0-W1.3-BL_DLW21 139.702,24.104 r270 top
U12 "" WFBGA-200_L14.5-W10.0-BL_MT53D512M32D2DS 149.815,101.752 r0 top locked
U13 "" DFN1006-2L-RD 138.864,19.231 r0 top
U14 "" DFN1006-2L-RD 140.815,19.222 r180 top
U15 "" WFBGA-200_L14.5-W10.0-BL_MT53D512M32D2DS 131.887,82.431 r90 top locked
U16 "" DFN1006-2L-RD 117.248,112.51 r0 top
U17 "" DFN1006-2L-RD 108.537,101.502 r270 top
U18 "" QFN-12_L3.0-W2.0-P0.5-TL_NB680 39.256,78.262 r90 top
U19 "" QFN-12_L3.0-W2.0-P0.5-TL_NB680 53.163,61.633 r0 top
U20 "" DFN2510-10_L2.5-W1.0-P0.50-BL 114.488,17.387 r180 top
U21 "" DFN2510-10_L2.5-W1.0-P0.50-BL 108.899,17.826 r180 top
U22 "RK860-3" WLCSP-20_L2.0-W1.6-R5-C4-P0.40-TL 191.869,29.461 r0 top
U23 "RK860-2" WLCSP-20_L2.0-W1.6-R5-C4-P0.40-TL 179.923,7.714 r0 top
U24 "RK860-2" WLCSP-20_L2.0-W1.6-R5-C4-P0.40-TL 184.447,38.887 r270 top
U25 "" SOT-23-5_L2.9-W1.6-P0.95-LS2.8-BL 213.56,19.023 r90 top
U26 "" SOT-23-5_L2.9-W1.6-P0.95-LS2.8-TL 200.407,14.741 r180 top
U27 "" SOT-23-5_L2.9-W1.6-P0.95-LS2.8-TL 200.462,20.426 r180 top
U28 "TPS566242DRLR" SOT-666-6_L1.6-W1.2-P0.50-LS1.6-BL -439.156,504.879 r0 top
U29 "" DFN1006-2L-RD 119.884,101.428 r270 top
U30 "ESD5341N" DFN1006-2L-RD 202.606,125.282 r180 top
U31 "ESD5341N" DFN1006-2L-RD 204.971,125.282 r0 top
U32 "SIT3232EEUE" TSSOP-16_L5.0-W4.4-P0.65-LS6.4-BL 683.923,-321.503 r180 top
U33 "" DFN1006-2L-RD 96.789,101.396 r270 top
U34 "TPS566247DRLR" SOT-5X3-6_W1.6-L1.2-P0.50-LS1.6-BL 16.137,91.057 r0 top
U35 "" QFN-60_L7.0-W7.0-P0.40-TL-EP3.4 22.569,115.575 r90 top
U36 "TPS563257DRLR" SOT-666-6_L1.6-W1.2-P0.50-LS1.6-BR 247.019,92.743 r0 top
U37 "12Mhz" CRYSTAL-SMD_4P-L3.2-W2.5-BL 32.761,114.312 r90 top
U38 "MIC5377YC5" SC-70-5 48.32,95.109 r270 top
U39 "PTPS62918RPYR" RPY0014A-MFG 232.877,84.671 r270 top
U40 "PTPS62918RPYR" RPY0014A-MFG 287.528,53.824 r270 top
U41 "" WSON-8_L6.0-W8.0-P1.27-BL-EP 12.889,105.416 r0 top
U42 "LM5066PMHX/NOPB" PWP0028A_L 27.479,36.146 r90 top
U43 "MCP23017T-E/SO" FP-C04-052-MFG 80.903,101.947 r90 top
U44 "MAX14830ETM+T" TQFN-48_L7.0-W7.0-P0.50-BL-EP5.5 55.389,109.752 r180 top
U45 "LAN8840_QFN-48_TEST" QFN-48_7x7_EP5.1x5.1 278.424,36.953 r90 top value=LAN8840
U46 "3.6864MHz" HC-49S_L11.4-W4.5-LS12.5 64.705,109.54 r270 top
U47 "DP83869HMRGZT" FP-RGZ0048B-IPC_A 235.637,36.085 r180 top
U48 "PTPS62918RPYR" RPY0014A-MFG 266.469,115.465 r0 top
U49 "DP83869HMRGZT" FP-RGZ0048B-IPC_A 231.241,55.205 r180 top
U50 "VSC8504XKS-05" FP-VSC8504XKS-05-IPC_C 261.419,51.879 r270 top locked
U51 "" SOT-5X3-6_W1.6-L1.2-P0.50-LS1.6-BL 239.279,104.414 r90 top
U52 "PTPS62918RPYR" RPY0014A-MFG 241.033,71.104 r180 top
U53 "" SOT-5X3-6_W1.6-L1.2-P0.50-LS1.6-BL 224.784,104.036 r90 top
U54 "TXU0101DCKR" FP-DCK0006A-MFG 44.915,107.559 r180 top
U55 "TXU0101DCKR" FP-DCK0006A-MFG 84.414,114.63 r270 top
U56 "TXU0101DCKR" FP-DCK0006A-MFG 74.745,120.091 r270 top
U57 "TXU0101DCKR" FP-DCK0006A-MFG 75.008,114.699 r270 top
U58 "TXU0101DCKR" FP-DCK0006A-MFG 79.244,119.839 r270 top
U59 "TXU0101DCKR" FP-DCK0006A-MFG 84.185,119.979 r270 top
U60 "TXU0101DCKR" FP-DCK0006A-MFG 79.823,114.666 r270 top
U61 "TXU0101DCKR" FP-DCK0006A-MFG 88.614,119.949 r270 top
U62 "LM25116MHX/NOPB" PWP0020A_N 36.818,62.711 r180 top
U63 "ATECC608B-SSHDA-T" SOIC127P600X175-8N 22.353,101.96 r0 top
USB1 "" MINI-USB-SMD_XY-5PTP-MINIUSB 203.458,133.049 r180 top
USBC1 "TYPE-C-31-M-12" HRO_TYPE-C-31-M-12 2.808,116.755 r270 top
X1 "24MHz" CRYSTAL-SMD_4P-L3.2-W2.5-BL 167.836,96.977 r180 top
Y2 "25Mhz" FP-ABM8AIG-MFG 233.194,45.001 r0 top
Y3 "DSC1123CI2-125.0000T" FP-C04-1007-MFG 266.809,62.879 r270 top
Y4 "25Mhz" FP-ABM8AIG-MFG 227.855,63.044 r180 top

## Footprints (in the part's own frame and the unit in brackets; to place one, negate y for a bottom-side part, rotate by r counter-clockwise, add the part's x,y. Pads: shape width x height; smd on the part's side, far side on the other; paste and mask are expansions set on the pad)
62900416021 [mm] "USB 2.0 SMT Type A Horizontal"
  rect 1.12x2.88 smd: 1(-3.5,6.95) 2(-1,6.95) 3(1,6.95) 4(3.5,6.95)
  round 3.45 hole 2.3: Shell(-6.57,3.28) Shell(6.57,3.28)
  silkscreen extent -7.25,-7 7.29,7, body extent -7.81,-7 7.81,8.41, height 7.81
692122030100 [mm] "USB 3.0 Type A Horizontal SMD"
  rect 0.9x2.6 smd: 1(-3.75,8.67) 2(-1.25,8.67) 3(1.25,8.67) 4(3.75,8.67)
  rect 0.9x2.15 smd: 5(5,8.895) 6(2.5,8.895) 7(0,8.895) 8(-2.5,8.895) 9(-5,8.895)
  round 2 hole 2 unplated: MH1(-3.4,3.45) MH2(3.4,3.45)
  oval 2.52x3.4 hole 1.12 slot 2 at 90 deg: Shell(-6.8,3.45) Shell(6.8,3.45)
  silkscreen extent -7.55,-8.33 7.55,8.33, body extent -7.55,-8.33 7.55,9.47, height 7.95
